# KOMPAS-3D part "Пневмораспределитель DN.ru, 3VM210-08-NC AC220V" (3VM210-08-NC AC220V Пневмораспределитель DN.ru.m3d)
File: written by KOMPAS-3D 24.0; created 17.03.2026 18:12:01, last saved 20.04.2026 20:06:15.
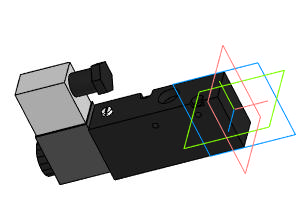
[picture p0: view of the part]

Document properties: Автор: R2D2; Полное имя файла: E:\Работа\Зайцев\Аксессуары для пневмоприводов\Пневмораспределители DN.ru\3VM210-08-NC Пневмораспределитель DN.RU\AC220V\3VM210-08-NC AC220V Пневмораспределитель DN.ru.m3d

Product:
- Part/product: Пневмораспределитель DN.ru  | designation 3VM210-08-NC AC220V
    Масса: 0.3
    Раздел спецификации: Прочие изделия
    Примечание: D290-00376

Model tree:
1. Операция без истории:1

Expressions: 3VM210-08-NC AC220V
